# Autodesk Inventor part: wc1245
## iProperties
Shininess: 64.0
Length Units: 11272
Angle Units: 11279
Time Units: 11290
Mass Units: 11286
Length Display Precision: 3
Angle Display Precision: 2
Compacted: True
Part Number: wc1245
Document SubType Name: Modeling
Created: 2004-08
Designer: John Blackburn
Manufacturer: Standard
Standards Organization: Custom
Material: Aluminum-6061
Density: 0.0
Volumn: 0.0
Area: 0.0
PropertySet Name: Model Information
Control State: 0
Master: False
Checked Out: False
Author: John Blackburn
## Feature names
1. Base1
